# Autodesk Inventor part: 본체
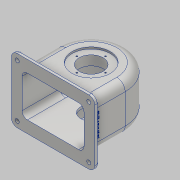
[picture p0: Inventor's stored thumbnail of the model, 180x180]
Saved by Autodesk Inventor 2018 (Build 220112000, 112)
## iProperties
Created: 2022-09
Part Number: 본체
Material: 알루미늄 6061
Document SubType Name: Modeling
Designer: home
Density: 2.7 g/cm^3
Appearance: 알루미늄 - 평지
Author: home
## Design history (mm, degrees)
sketch "스케치1"
  geometry: L1 (-57, 0)-(57, 0); L2 (57, 0)-(57, -64); L3 (57, -64)-(-57, -64); L4 (-57, -64)-(-57, 0); A1 r 57 centre (0, 0) between (57, 0) and (-57, 0); 1 further point
  constraints: 8 end point, 2 parallel, 2 point on circle, 1 centre point, 1 coincident, 1 horizontal, 1 perpendicular
  dimensions: "d0" = 114 diameter of A1; "d1" = 64 distance of L1.end L2.end
extrude "돌출1" new body sketch "스케치1" stored distance "d2" = 78; taper "d3" = 0 deg
feature "쉘1" dims "d4" = 5
sketch "스케치2"
  geometry: L1 (-57, 0)-(-57, -64) reference; L2 (-57, -64)-(57, -64) reference; L3 (57, -64)-(57, 0) reference; C1 r 31 at (0, 0); A1 r 57 centre (0, 0) between (57, 0) and (-57, 0) reference; 1 further point
  constraints: 1 centre point, 1 coincident
  dimensions: "d5" = 62 diameter of C1
extrude "돌출2" join sketch "스케치2" distance "d6" = 15; taper "d7" = 0 deg
hole "구멍1" diameter "d10" = 35; stored, may be unused: countersink angle "d14" = 90 deg, drill point angle "d16" = 118 deg; dims "d8" = 10, "d9" = 10, "d11" = 6, "d12" = 40, "d13" = 16, "d15" = 30
sketch "스케치3"
  geometry: A1 r 24 centre (0, 0) between (0, 24) and (-24, 0); 3 further points
  constraints: 4 point on circle, 1 centre point, 1 coincident
  dimensions: "d17" = 48 diameter of A1
hole "구멍2" sketch "스케치3" at (0, 24), (-24, 0), (0, -24), (24, 0) diameter "d18" = 2.459; stored, may be unused: countersink angle "d22" = 90 deg, drill point angle "d24" = 118 deg; dims "d19" = 7, "d20" = 40, "d21" = 16, "d23" = 9
node "작업 평면1"
sketch "스케치4"
  geometry: C1 r 28 at (0, 0); 1 further point
  constraints: 1 centre point, 1 coincident
  dimensions: "d26" = 56 diameter of C1
extrude "돌출3" join sketch "스케치4" distance "d27" = 19; taper "d28" = 30 deg
sketch "스케치5"
  geometry: C1 r 32 at (0, 0); 1 further point
  constraints: 1 centre point, 1 coincident
  dimensions: "d29" = 64 diameter of C1
extrude "돌출4" cut sketch "스케치5" distance "d30" = 3; taper "d31" = 0 deg
hole "구멍3" diameter "d34" = 40; stored, may be unused: countersink angle "d38" = 90 deg, drill point angle "d40" = 118 deg; dims "d32" = 10, "d33" = 10, "d35" = 7, "d36" = 40, "d37" = 16, "d39" = 30
sketch "스케치6"
  geometry: L1 (-3, 15)-(117, 15); L2 (127, 5)-(127, -83); L3 (117, -93)-(-3, -93); L4 (-13, -83)-(-13, 5); L5 (-13, 15)-(127, -93); L6 (127, 15)-(-13, -93); L7 (5, -73)-(5, -5) reference; L8 (5, -5)-(109, -5) reference; L9 (109, -5)-(109, -73) reference; L10 (109, -73)-(5, -73) reference; L11 (114, -78)-(114, 0) reference; L12 (0, 0)-(114, 0) reference; L13 (0, -78)-(0, 0) reference; L14 (114, -78)-(0, -78) reference; C1 r 3.3 at (117, 5); C2 r 3.3 at (117, -83); C3 r 3.3 at (-3, 5); C4 r 3.3 at (-3, -83); A1 r 10 centre (117, 5) between (127, 5) and (117, 15); A2 r 10 centre (117, -83) between (117, -93) and (127, -83); A3 r 10 centre (-3, -83) between (-13, -83) and (-3, -93); A4 r 10 centre (-3, 5) between (-3, 15) and (-13, 5); 1 further point
  constraints: 12 end point, 8 centre point, 8 point on circle, 8 point on line, 8 tangent, 4 coincident, 3 equal radius, 2 midpoint, 2 parallel, 1 horizontal, 1 perpendicular
  dimensions: "d41" = 140 distance of L5.end L6.end; "d42" = 108 distance of L6.start L5.end; "d43" = 10 radius of A1; "d44" = 6.6 diameter of C1; "d45" = 6.6 diameter of C2; "d46" = 6.6 diameter of C3; "d47" = 6.6 diameter of C4
extrude "돌출5" join sketch "스케치6" distance "d48" = 7; taper "d49" = 0 deg
fillet "모깎기1" dims "d50" = 14
fillet "모깎기2" dims "d51" = 3
sketch "스케치7"
  geometry: C1 r 1.23 at (24, 0) reference; A1 r 24 centre (0, 0) between (0, 24) and (-24, 0); 3 further points
  constraints: 3 point on circle, 2 coincident, 1 centre point
  dimensions: "d52" = 48 diameter of A1
hole "구멍4" sketch "스케치7" at (0, 24), (-24, 0), (0, -24), (24, 0) diameter "d53" = 2.459; stored, may be unused: countersink angle "d57" = 90 deg, drill point angle "d59" = 118 deg; dims "d54" = 7, "d55" = 40, "d56" = 16, "d58" = 9
node "작업 평면3"
  node "작업 평면2"
sketch "스케치8"
  geometry: C1 r 6 at (0, 0); 1 further point
  constraints: 1 centre point, 1 coincident
  dimensions: "d61" = 12 diameter of C1
extrude "돌출6" join sketch "스케치8" stored distance "d62" = 7; taper "d63" = 0 deg
hole "구멍5" diameter "d66" = 5.188; stored, may be unused: countersink angle "d70" = 90 deg, drill point angle "d72" = 118 deg; dims "d64" = 10, "d65" = 10, "d67" = 20, "d68" = 40, "d69" = 16, "d71" = 20
fillet "모깎기3" dims "d73" = 1
fillet "모깎기4" dims "d74" = 9
sketch "스케치9"
  geometry: L1 (69, -64)-(-19, -64) reference; L2 (25, -64)-(25, -47); L3 (25, -47)-(-14, -47); 1 further point
  constraints: 4 end point, 1 coincident, 1 horizontal, 1 midpoint, 1 vertical, 1 other
  dimensions: "d75" = 17 distance of L2.start L2.end; "d79" = 39 distance of L3.start L3.end
feature "엠보싱1" sketch "스케치9" dims "d0" = 114, "d1" = 64, "d14" = 90 deg, "d76" = 0.5, "d77" = 0
fillet "모깎기5" dims "d78" = 0.6
fillet "모깎기6" dims "d80" = 3
node "솔리드1"
node "투영된 루프1"
node "투영된 루프2"
other parameters: "d25" = -19, "d60" = 3
